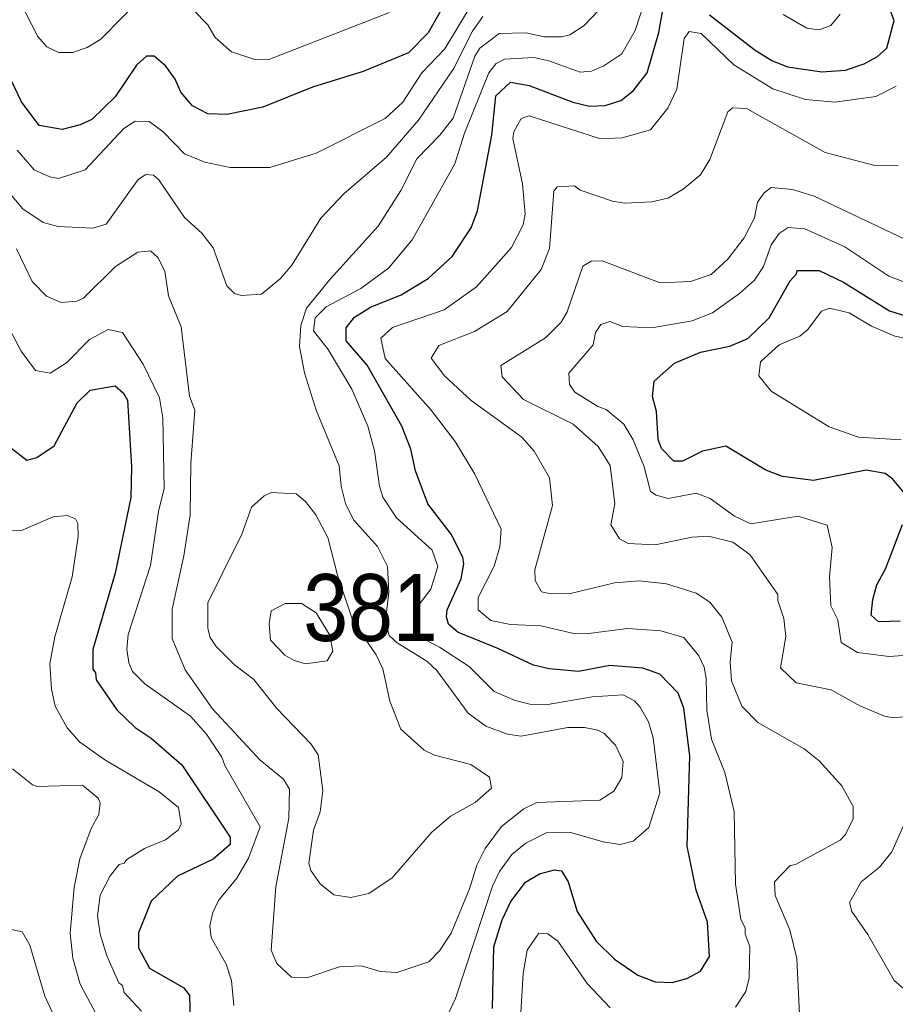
# Model space of a CAD drawing. Extents: x 673.3 to 698.5, y 6984.3 to 7012.3.
# Drawn here: x 693.582 to 694.629, y 6995.156 to 6996.334 of the extents above; entities that cross this region are included whole.
import ezdxf

# ---------------------------------------------------------------- set-up
doc = ezdxf.new("R2010")
doc.units = 0
doc.header["$LTSCALE"] = 0.032
doc.layers.add('1', color=7, linetype='Continuous', lineweight=25)
doc.layers.add('2', color=7, linetype='Continuous', lineweight=13)
doc.layers.add('21', color=7, linetype='Continuous')

msp = doc.modelspace()

# ---------------------------------------------------------------- linework, layer by layer
at = {"layer": '1'}
for points in [[(694.1035, 6996.3774), (694.0703, 6996.3179), (694.0465, 6996.2943), (693.9923, 6996.2717), (693.932, 6996.2532), (693.8723, 6996.2292), (693.8295, 6996.2203), (693.8067, 6996.2213), (693.7882, 6996.2307), (693.7743, 6996.247), (693.7675, 6996.2627), (693.7563, 6996.2781), (693.7424, 6996.29), (693.7334, 6996.2901), (693.7215, 6996.2792), (693.6957, 6996.2413), (693.6681, 6996.2144), (693.654, 6996.208), (693.6324, 6996.2026), (693.6048, 6996.2073), (693.5839, 6996.2357), (693.556, 6996.2933)], [(694.4066, 6996.3394), (694.4613, 6996.2973), (694.481, 6996.2851), (694.5, 6996.2773), (694.5408, 6996.2715), (694.5693, 6996.2734), (694.5916, 6996.281), (694.6074, 6996.2898), (694.6186, 6996.2996), (694.6276, 6996.3326), (694.6161, 6996.3637)], [(694.191, 6996.2552), (694.2432, 6996.2353), (694.2632, 6996.2302), (694.2817, 6996.231), (694.3004, 6996.2372), (694.3154, 6996.2486), (694.3319, 6996.2701), (694.3462, 6996.3184), (694.3506, 6996.3431)], [(694.1471, 6995.1511), (694.1487, 6995.2249), (694.1587, 6995.2574), (694.1692, 6995.2792), (694.1864, 6995.3022), (694.2035, 6995.3124), (694.2211, 6995.3172), (694.2297, 6995.3158), (694.2375, 6995.3027), (694.2482, 6995.2672), (694.2711, 6995.2315), (694.293, 6995.2103), (694.3208, 6995.1909), (694.3418, 6995.1829), (694.362, 6995.1822), (694.3794, 6995.1871), (694.3959, 6995.1957), (694.4066, 6995.2135), (694.4044, 6995.2545), (694.3907, 6995.2928), (694.38, 6995.3454), (694.3832, 6995.4535), (694.3759, 6995.5102), (694.3693, 6995.5281), (694.3473, 6995.5509), (694.327, 6995.5583), (694.2876, 6995.5615), (694.2498, 6995.5543), (694.2149, 6995.5574), (694.196, 6995.5618), (694.1535, 6995.5818), (694.1213, 6995.5948), (694.106, 6995.601), (694.0945, 6995.6109), (694.0922, 6995.6196), (694.0927, 6995.6278), (694.1097, 6995.6652), (694.1128, 6995.6829), (694.1118, 6995.6908), (694.0975, 6995.7184), (694.0696, 6995.7548), (694.0552, 6995.7943), (694.0493, 6995.82), (694.0386, 6995.8477), (693.9974, 6995.9204), (693.9722, 6995.9497), (693.972, 6995.9652), (693.982, 6995.9779), (694.0011, 6995.9898), (694.0377, 6996.0048), (694.07, 6996.0243), (694.0988, 6996.0507), (694.1217, 6996.085), (694.1292, 6996.105), (694.1462, 6996.1956), (694.151, 6996.2425), (694.1688, 6996.2591), (694.191, 6996.2552)], [(694.3403, 6995.9013), (694.3646, 6995.9231), (694.3957, 6995.9362), (694.431, 6995.9434), (694.4524, 6995.9525), (694.4779, 6995.9771), (694.503, 6996.0216), (694.5108, 6996.0297), (694.5113, 6996.0338), (694.5377, 6996.0337), (694.5667, 6996.0199), (694.6221, 6995.9857), (694.6574, 6995.9745)], [(693.5708, 6995.8221), (693.5902, 6995.8068), (693.6022, 6995.81), (693.6228, 6995.824), (693.6503, 6995.8755), (693.6661, 6995.8908), (693.696, 6995.896), (693.7058, 6995.8871), (693.7105, 6995.8788), (693.7154, 6995.7988)], [(694.6395, 6995.7679), (694.6256, 6995.7848), (694.6166, 6995.7911), (694.5939, 6995.7951), (694.5311, 6995.7825), (694.4938, 6995.7875), (694.4739, 6995.7951), (694.4263, 6995.8236), (694.3984, 6995.8179), (694.3742, 6995.8059), (694.364, 6995.8059), (694.3493, 6995.8211), (694.3453, 6995.8316), (694.3433, 6995.8653), (694.3385, 6995.8829), (694.3403, 6995.9013)], [(693.7154, 6995.7988), (693.7146, 6995.7624), (693.696, 6995.6718), (693.6691, 6995.5805), (693.6691, 6995.5569), (693.6723, 6995.5527), (693.6732, 6995.5444), (693.6978, 6995.5084), (693.7197, 6995.4872), (693.7388, 6995.4746), (693.7757, 6995.4426), (693.8335, 6995.356), (693.8334, 6995.3474), (693.8129, 6995.3299), (693.7703, 6995.3093), (693.7389, 6995.2794), (693.7237, 6995.2415), (693.7237, 6995.2236), (693.7368, 6995.1992), (693.7778, 6995.1757), (693.7847, 6995.1667), (693.7855, 6995.1386)], [(694.6345, 6995.6144), (694.6086, 6995.6136), (694.5999, 6995.6214), (694.6019, 6995.6403), (694.6069, 6995.6577), (694.6175, 6995.6776), (694.6373, 6995.7301)]]:
    msp.add_lwpolyline(points, dxfattribs=at)
at = {"layer": '2'}
for points in [[(694.0733, 6995.6528), (694.0817, 6995.6798), (694.0751, 6995.6994), (694.0324, 6995.738), (694.0158, 6995.7627), (694.0118, 6995.776), (694.0061, 6995.818), (693.9979, 6995.8477), (693.9789, 6995.8918), (693.9506, 6995.9392), (693.9329, 6995.9615), (693.9352, 6995.9771), (693.948, 6995.9903), (693.9896, 6996.0123), (694.0226, 6996.0365), (694.051, 6996.0703), (694.1021, 6996.1615), (694.1136, 6996.1979), (694.1427, 6996.2703), (694.1514, 6996.2814), (694.1614, 6996.2864), (694.1967, 6996.2887), (694.2146, 6996.2847), (694.2519, 6996.2709), (694.2655, 6996.2723), (694.2803, 6996.2784), (694.3018, 6996.293), (694.3176, 6996.3207), (694.3351, 6996.3749)], [(693.7323, 6996.3651), (693.6787, 6996.3105), (693.6623, 6996.3004), (693.6449, 6996.2945), (693.6286, 6996.2944), (693.614, 6996.3013), (693.6034, 6996.3135), (693.5819, 6996.3555)], [(694.0239, 6996.3424), (693.8798, 6996.2862), (693.864, 6996.2857), (693.835, 6996.2954), (693.8156, 6996.3126), (693.8068, 6996.3276), (693.7712, 6996.3642)], [(693.5788, 6996.1778), (693.5988, 6996.1541), (693.6176, 6996.1458), (693.6281, 6996.1439), (693.6598, 6996.1543), (693.706, 6996.2036), (693.7198, 6996.2122), (693.7366, 6996.212), (693.7534, 6996.1996), (693.7789, 6996.1733), (693.8029, 6996.1632), (693.8334, 6996.157), (693.8807, 6996.157), (693.9364, 6996.1741), (694.0188, 6996.2154), (694.0397, 6996.2353), (694.0627, 6996.2703), (694.0902, 6996.2988), (694.1238, 6996.3553)], [(693.6501, 6995.997), (693.658, 6996.0007), (693.6963, 6996.0384), (693.7228, 6996.0558), (693.7379, 6996.0574), (693.747, 6996.0493), (693.7553, 6996.0331), (693.7595, 6996.0033), (693.7748, 6995.9663), (693.7847, 6995.8833), (693.7911, 6995.8669), (693.7863, 6995.8028), (693.7856, 6995.7415), (693.7781, 6995.6926), (693.7642, 6995.6289), (693.7642, 6995.5936), (693.7796, 6995.5561), (693.8122, 6995.5097), (693.8693, 6995.4483), (693.8972, 6995.4253), (693.9043, 6995.4133), (693.9036, 6995.3786), (693.888, 6995.2968), (693.8823, 6995.2208), (693.8892, 6995.2051), (693.9069, 6995.1886), (693.925, 6995.1878), (693.9641, 6995.2008), (693.9899, 6995.2023), (694.0131, 6995.1955), (694.0328, 6995.1943), (694.0708, 6995.2069), (694.0837, 6995.2203), (694.0976, 6995.2412), (694.1198, 6995.2943), (694.1282, 6995.3227), (694.1382, 6995.3427), (694.158, 6995.3689), (694.1844, 6995.3899), (694.2003, 6995.3974), (694.2754, 6995.4003), (694.2922, 6995.4112), (694.3017, 6995.4273), (694.3034, 6995.4464), (694.2944, 6995.4662), (694.2805, 6995.4801), (694.273, 6995.4842), (694.2573, 6995.4874), (694.2372, 6995.4874), (694.1812, 6995.4769), (694.1652, 6995.4794), (694.1393, 6995.4888), (694.1179, 6995.5045), (694.0807, 6995.5554), (694.0686, 6995.5666), (694.0332, 6995.5886), (694.0237, 6995.5972), (694.0192, 6995.6143), (694.0233, 6995.6491), (694.0217, 6995.6798), (694.0097, 6995.7036), (693.9807, 6995.7356), (693.9715, 6995.7553), (693.9662, 6995.776), (693.9638, 6995.8001), (693.9362, 6995.8669), (693.9224, 6995.9116), (693.9161, 6995.9429), (693.9177, 6995.9679), (693.9247, 6995.9888), (693.9528, 6996.0236), (694.0102, 6996.0868), (694.0373, 6996.1294), (694.0568, 6996.1673), (694.084, 6996.1956), (694.0999, 6996.2161), (694.1258, 6996.2902), (694.1321, 6996.2997), (694.155, 6996.3173), (694.1869, 6996.318), (694.2094, 6996.3133), (694.2298, 6996.3132), (694.2394, 6996.3158), (694.2569, 6996.3268), (694.2743, 6996.345)], [(694.4948, 6996.3401), (694.5232, 6996.3236), (694.5377, 6996.3215), (694.5516, 6996.3269), (694.5631, 6996.3405)], [(694.1355, 6996.3374), (694.1231, 6996.32), (694.1006, 6996.2749), (694.0588, 6996.2136), (694.0204, 6996.1695), (693.9693, 6996.1256), (693.9418, 6996.0965), (693.9072, 6996.0402), (693.8937, 6996.0241), (693.8707, 6996.0054), (693.8466, 6996.0038), (693.8386, 6996.0062), (693.8293, 6996.0153), (693.8131, 6996.0607), (693.7994, 6996.0785), (693.7789, 6996.0973), (693.748, 6996.1423), (693.7416, 6996.148), (693.7326, 6996.1487), (693.7232, 6996.1426), (693.6849, 6996.0892), (693.6693, 6996.0844), (693.6276, 6996.0866), (693.6099, 6996.0911), (693.5856, 6996.1075), (693.5519, 6996.1468)], [(694.6298, 6996.2544), (694.6054, 6996.2418), (694.5567, 6996.235), (694.5213, 6996.2384), (694.4825, 6996.251), (694.4356, 6996.2797), (694.3967, 6996.3173), (694.3824, 6996.3195), (694.3765, 6996.3114), (694.3675, 6996.2507), (694.3568, 6996.2279), (694.3362, 6996.202)], [(694.5144, 6995.1442), (694.511, 6995.2108), (694.5027, 6995.2453), (694.4852, 6995.2865), (694.4842, 6995.3025), (694.5033, 6995.3221), (694.5095, 6995.3232), (694.5628, 6995.3526), (694.5692, 6995.3593), (694.5784, 6995.3778), (694.5785, 6995.3929), (694.5647, 6995.4175), (694.5379, 6995.4475), (694.52, 6995.4619), (694.4644, 6995.4933), (694.4455, 6995.5129), (694.4328, 6995.5431), (694.4312, 6995.5656), (694.4338, 6995.5893), (694.4214, 6995.6193), (694.407, 6995.6371), (694.3908, 6995.6477), (694.3553, 6995.6591), (694.3227, 6995.6625), (694.2931, 6995.6601), (694.2403, 6995.6474), (694.2173, 6995.6471), (694.2058, 6995.6496), (694.1982, 6995.663), (694.1976, 6995.6757), (694.2187, 6995.7529), (694.2153, 6995.7858), (694.1969, 6995.8178), (694.182, 6995.8343), (694.1216, 6995.8785), (694.0897, 6995.908), (694.0738, 6995.9289), (694.083, 6995.9442), (694.1256, 6995.9607), (694.1647, 6995.9849), (694.2053, 6996.0348), (694.2153, 6996.0602), (694.2203, 6996.1288), (694.2243, 6996.1339), (694.2451, 6996.1349), (694.2518, 6996.1299), (694.2906, 6996.1168), (694.3052, 6996.1145), (694.3375, 6996.116), (694.3569, 6996.1204), (694.3753, 6996.131), (694.396, 6996.1484), (694.4071, 6996.1664), (694.4287, 6996.2235), (694.4343, 6996.2283), (694.4509, 6996.2276), (694.5448, 6996.175), (694.6042, 6996.1592), (694.6322, 6996.1591)], [(694.3362, 6996.202), (694.3022, 6996.1923), (694.2763, 6996.1911), (694.1909, 6996.2186), (694.1813, 6996.2154), (694.1725, 6996.1995), (694.1715, 6996.1916), (694.1828, 6996.1376), (694.1861, 6996.1013), (694.1836, 6996.0885), (694.1699, 6996.0614), (694.1281, 6996.0141), (694.0895, 6995.9868), (694.0276, 6995.9655), (694.0135, 6995.9527), (694.0186, 6995.9287), (694.0739, 6995.8667), (694.1024, 6995.8292), (694.126, 6995.7902), (694.1575, 6995.7243), (694.1559, 6995.7034), (694.1491, 6995.6801), (694.13, 6995.6429), (694.13, 6995.6278), (694.1453, 6995.6152), (694.1688, 6995.6104), (694.2049, 6995.6087), (694.2442, 6995.5998), (694.2589, 6995.5991), (694.3088, 6995.6055), (694.3485, 6995.603), (694.3759, 6995.5948), (694.3938, 6995.5729), (694.4002, 6995.5594), (694.4027, 6995.5463), (694.4036, 6995.508), (694.4091, 6995.4734), (694.4248, 6995.4335), (694.4363, 6995.3869), (694.4378, 6995.2999), (694.444, 6995.2575), (694.4491, 6995.2477), (694.4493, 6995.2402), (694.4548, 6995.2252), (694.454, 6995.1878), (694.4502, 6995.1713), (694.4376, 6995.1526)], [(694.6403, 6996.0711), (694.5317, 6996.1225), (694.506, 6996.1308), (694.4804, 6996.1332), (694.4719, 6996.1265), (694.4641, 6996.1156), (694.4605, 6996.0969), (694.4481, 6996.0727), (694.4284, 6996.0472), (694.4085, 6996.029), (694.3841, 6996.0205), (694.3476, 6996.0191), (694.2782, 6996.0452), (694.265, 6996.0451), (694.255, 6996.039), (694.2366, 6995.9842), (694.2294, 6995.972), (694.2104, 6995.9534), (694.1569, 6995.9203), (694.1587, 6995.9067), (694.1843, 6995.8794), (694.2437, 6995.85), (694.2736, 6995.8234), (694.2878, 6995.8004), (694.2936, 6995.7549), (694.2888, 6995.7296), (694.2991, 6995.7129), (694.3094, 6995.7072), (694.3418, 6995.7057), (694.3859, 6995.7147), (694.4055, 6995.7162), (694.4345, 6995.7089), (694.455, 6995.6942), (694.4882, 6995.6462), (694.4883, 6995.6392), (694.4956, 6995.6175), (694.498, 6995.596), (694.4916, 6995.5585), (694.5102, 6995.5405), (694.552, 6995.5322), (694.5863, 6995.5133), (694.616, 6995.5008), (694.6261, 6995.4989), (694.6717, 6995.5032)], [(694.2875, 6995.9728), (694.3029, 6995.967), (694.3374, 6995.9653), (694.3859, 6995.9737), (694.4101, 6995.9833), (694.4426, 6996.0064), (694.4604, 6996.0224), (694.4714, 6996.0386), (694.4803, 6996.0643), (694.4901, 6996.0779), (694.5008, 6996.0851), (694.5208, 6996.0835), (694.5684, 6996.0622), (694.6213, 6996.0272), (694.6409, 6996.0194)], [(693.5777, 6996.0598), (693.5967, 6996.0207), (693.6137, 6996.0031), (693.6313, 6995.9956), (693.6501, 6995.997)], [(693.5483, 6996.003), (693.5833, 6995.9372), (693.6007, 6995.9142), (693.6181, 6995.9111), (693.6375, 6995.9235), (693.6653, 6995.9512), (693.6876, 6995.9631), (693.7047, 6995.9597), (693.7295, 6995.9218), (693.7488, 6995.8816), (693.7528, 6995.8577), (693.7546, 6995.773), (693.7477, 6995.7454), (693.7382, 6995.681), (693.7114, 6995.5985), (693.7098, 6995.581), (693.712, 6995.5646), (693.7164, 6995.5542), (693.7313, 6995.5396), (693.7861, 6995.5006), (693.8052, 6995.4791), (693.8236, 6995.4519), (693.8271, 6995.4416), (693.8693, 6995.3685), (693.8554, 6995.3308), (693.8412, 6995.3071), (693.8195, 6995.2803), (693.8128, 6995.266), (693.8091, 6995.2502), (693.8108, 6995.2361), (693.8285, 6995.2043), (693.8351, 6995.1845), (693.8376, 6995.1547)], [(694.644, 6995.952), (694.6284, 6995.9553), (694.6005, 6995.9671), (694.5738, 6995.9833), (694.55, 6995.9889), (694.5407, 6995.9851), (694.5243, 6995.9633), (694.5146, 6995.9551), (694.49, 6995.945), (694.4677, 6995.9245), (694.4655, 6995.9079), (694.4802, 6995.8896), (694.5496, 6995.8468), (694.5847, 6995.8343), (694.6357, 6995.8311)], [(694.655, 6995.5747), (694.6216, 6995.5722), (694.5838, 6995.5769), (694.564, 6995.5887), (694.56, 6995.6158), (694.5517, 6995.6327), (694.5501, 6995.6675), (694.5534, 6995.7027), (694.5475, 6995.7294), (694.5126, 6995.7399), (694.456, 6995.731), (694.4367, 6995.74), (694.4075, 6995.7611), (694.3905, 6995.7675), (694.3573, 6995.7611), (694.3428, 6995.7649), (694.336, 6995.7695), (694.3284, 6995.7991), (694.3155, 6995.8314), (694.3041, 6995.85), (694.283, 6995.8677), (694.2731, 6995.8711), (694.2457, 6995.8882), (694.239, 6995.8974), (694.2385, 6995.9112), (694.2674, 6995.9447), (694.2701, 6995.9597), (694.2766, 6995.9694), (694.2875, 6995.9728)], [(693.7714, 6995.3915), (693.7486, 6995.4102), (693.6835, 6995.4485), (693.6532, 6995.4701), (693.6385, 6995.4868), (693.6239, 6995.5129), (693.6195, 6995.5329), (693.6177, 6995.5634), (693.6235, 6995.5956), (693.6444, 6995.6676), (693.6517, 6995.7158), (693.651, 6995.7314), (693.6485, 6995.7366), (693.6383, 6995.7406), (693.6218, 6995.739), (693.5837, 6995.7227), (693.5691, 6995.7223)], [(694.0934, 6995.1427), (694.1029, 6995.1631), (694.1473, 6995.2974), (694.1554, 6995.3151), (694.1703, 6995.3355), (694.1869, 6995.3489), (694.2114, 6995.3611), (694.2391, 6995.362), (694.2796, 6995.3503), (694.2999, 6995.3473), (694.3154, 6995.3514), (694.3342, 6995.3678), (694.3473, 6995.409), (694.3391, 6995.475), (694.3335, 6995.4939), (694.3239, 6995.5116), (694.3171, 6995.5191), (694.3033, 6995.5264), (694.2665, 6995.524), (694.2107, 6995.5143), (694.1916, 6995.5152), (694.1741, 6995.5195), (694.1493, 6995.5302), (694.1191, 6995.56), (694.0838, 6995.5834), (694.0585, 6995.5965), (694.0534, 6995.6106), (694.0532, 6995.6258), (694.0733, 6995.6528)], [(693.5729, 6995.4377), (693.5968, 6995.4187), (693.6026, 6995.4168), (693.6566, 6995.4182), (693.6757, 6995.4027), (693.678, 6995.397), (693.6763, 6995.3831), (693.6671, 6995.3663), (693.6537, 6995.33), (693.6469, 6995.2959), (693.6421, 6995.2411), (693.6452, 6995.2115), (693.6539, 6995.1803), (693.6814, 6995.1289)], [(693.7274, 6995.148), (693.7064, 6995.1702), (693.7048, 6995.1786), (693.7002, 6995.1819), (693.6857, 6995.2143), (693.6779, 6995.2401), (693.6748, 6995.262), (693.6779, 6995.2868), (693.69, 6995.3097), (693.7007, 6995.3235), (693.7065, 6995.3248), (693.7096, 6995.3292), (693.7309, 6995.3424), (693.7559, 6995.3529), (693.7717, 6995.3647), (693.7747, 6995.3722), (693.7714, 6995.3915)], [(694.6456, 6995.3851), (694.6246, 6995.3387), (694.6101, 6995.3201), (694.5882, 6995.3027), (694.574, 6995.2778), (694.577, 6995.2672), (694.5959, 6995.2396), (694.6274, 6995.1848), (694.6596, 6995.1572)], [(693.6268, 6995.1333), (693.6116, 6995.166), (693.5939, 6995.2271), (693.5845, 6995.2429), (693.5698, 6995.2462)], [(694.2879, 6995.1519), (694.2602, 6995.1809), (694.2252, 6995.2317), (694.2132, 6995.2404), (694.2026, 6995.2413), (694.1886, 6995.2209), (694.1838, 6995.1929), (694.1804, 6995.1399)]]:
    msp.add_lwpolyline(points, dxfattribs=at)
for points in [[(694.0967, 6995.3813), (694.1265, 6995.3977), (694.1459, 6995.4147), (694.1436, 6995.4279), (694.1213, 6995.4428), (694.0779, 6995.4543), (694.0654, 6995.4602), (694.0376, 6995.4853), (694.0244, 6995.5187), (694.0161, 6995.5575), (694.0078, 6995.5742), (693.9801, 6995.6149), (693.9618, 6995.6693), (693.9502, 6995.7146), (693.9359, 6995.7417), (693.9233, 6995.7576), (693.9125, 6995.7666), (693.8828, 6995.7684), (693.8742, 6995.7643), (693.8589, 6995.7507), (693.8468, 6995.7174), (693.8426, 6995.7089), (693.8066, 6995.6362), (693.8065, 6995.6057), (693.8096, 6995.5947), (693.8166, 6995.5842), (693.8387, 6995.562), (693.8616, 6995.5448), (693.8893, 6995.5098), (693.9298, 6995.4677), (693.9385, 6995.4545), (693.9442, 6995.4119), (693.941, 6995.3864), (693.933, 6995.3646), (693.9275, 6995.3249), (693.93, 6995.3161), (693.9412, 6995.3002), (693.9573, 6995.2873), (693.9778, 6995.2839), (693.9993, 6995.2888), (694.0271, 6995.3073), (694.0747, 6995.3622)], [(693.88, 6995.6114), (693.8824, 6995.6266), (693.8993, 6995.6354), (693.9185, 6995.6356), (693.9361, 6995.6245), (693.9525, 6995.5976), (693.9563, 6995.5786), (693.9492, 6995.5671), (693.9234, 6995.5634), (693.9098, 6995.5672), (693.8987, 6995.5736), (693.8816, 6995.5917)]]:
    msp.add_lwpolyline(points, close=True, dxfattribs=at)

# ---------------------------------------------------------------- texts
at = {"layer": '21', "width": 0.9}
msp.add_text('381', height=0.08, dxfattribs=at).set_placement((693.9209, 6995.5907))

doc.saveas('drawing.dxf')
